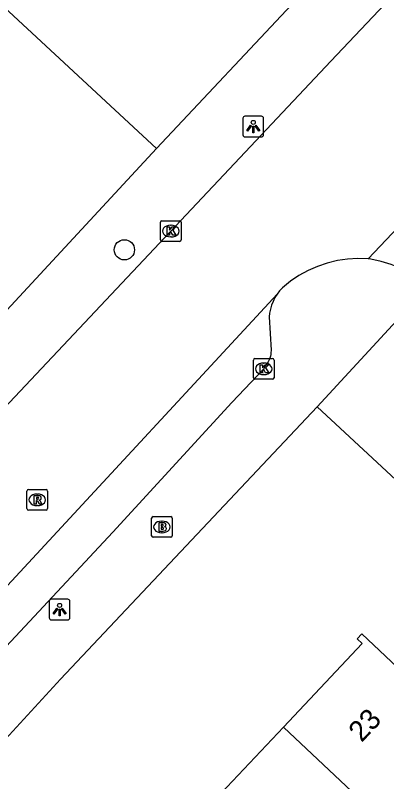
# Model space of a CAD drawing. Extents: x 159222 to 160346, y 381249 to 382166.
# Drawn here: x 159820.63 to 159838.58, y 381687.69 to 381724.77 of the extents above; entities that cross this region are included whole.
import ezdxf

# ---------------------------------------------------------------- set-up
doc = ezdxf.new("R2010")
doc.units = 0
for name, color, linetype in [('IMGEO_Boom', 7, 'Continuous'), ('IMGEO_Brandkraan', 7, 'Continuous'), ('IMGEO_Kolk', 7, 'Continuous'), ('IMGEO_Lichtpunt', 7, 'Continuous'), ('IMGEO_Pand', 7, 'Continuous'), ('IMGEO_Pand_nummerreeks', 7, 'Continuous'), ('IMGEO_Rijbaan_lokaal_gesloten', 7, 'Continuous'), ('IMGEO_Rijbaan_lokaal_open', 7, 'Continuous'), ('IMGEO_Rioolput', 7, 'Continuous'), ('IMGEO_Voetpad_open', 7, 'Continuous')]:
    doc.layers.add(name, color=color, linetype=linetype)

msp = doc.modelspace()

# ---------------------------------------------------------------- linework, layer by layer
at = {"layer": 'IMGEO_Boom'}
msp.add_circle((159825.903, 381713.424), 0.489, dxfattribs=at)
at = {"layer": 'IMGEO_Brandkraan'}
for p, q in [((159827.218, 381699.588), (159827.218, 381700.44)), ((159827.293, 381700.514), (159828.145, 381700.514)), ((159828.219, 381700.44), (159828.219, 381699.588)), ((159827.706, 381700.294), (159827.731, 381700.294)), ((159827.729, 381699.734), (159827.704, 381699.734)), ((159828.145, 381699.514), (159827.293, 381699.514))]:
    msp.add_line(p, q, dxfattribs=at)
for points in [[(159827.218, 381699.588), (159827.218, 381700.44)], [(159827.293, 381700.514), (159828.145, 381700.514)], [(159828.219, 381700.44), (159828.219, 381699.588)], [(159827.566, 381700.214), (159827.566, 381699.814), (159827.779, 381699.814)], [(159827.797, 381700.214), (159827.566, 381700.214)], [(159827.745, 381700.133), (159827.691, 381700.133), (159827.691, 381700.057)], [(159827.691, 381700.057), (159827.744, 381700.057)], [(159827.753, 381699.981), (159827.691, 381699.981), (159827.691, 381699.9)], [(159827.691, 381699.9), (159827.753, 381699.9)], [(159828.145, 381699.514), (159827.293, 381699.514)]]:
    msp.add_lwpolyline(points, dxfattribs=at)
for centre, radius, start, end in [((159827.295, 381700.438), 0.0765, 91.552, 178.448), ((159827.295, 381700.438), 0.0765, 91.552, 178.448), ((159828.143, 381700.438), 0.0765, 1.552, 88.448), ((159828.143, 381700.438), 0.0765, 1.552, 88.448), ((159827.746, 381700.095), 0.0379, 267.8285, 90.9355), ((159827.801, 381700.069), 0.145, 59.4692, 91.5367), ((159827.826, 381700.116), 0.0922, 285.5137, 58.1501), ((159827.831, 381699.924), 0.105, 301.3115, 78.989), ((159827.754, 381699.94), 0.0404, 269.8759, 90.5077), ((159827.785, 381700.065), 0.251, 268.6676, 293.5347), ((159827.295, 381699.59), 0.0765, 181.552, 268.448), ((159827.295, 381699.59), 0.0765, 181.552, 268.448), ((159828.143, 381699.59), 0.0765, 271.552, 358.448), ((159828.143, 381699.59), 0.0765, 271.552, 358.448)]:
    msp.add_arc(centre, radius, start, end, dxfattribs=at)
for centre, major_axis, ratio, start_param, end_param in [((159827.705, 381700.014), (-0.387, 0.002), 0.722429, 4.712389, 7.853982), ((159827.73, 381700.014), (-0.39, 0.002), 0.717154, 1.570796, 4.712389)]:
    msp.add_ellipse(centre, major_axis=major_axis, ratio=ratio, start_param=start_param, end_param=end_param, dxfattribs=at)
at = {"layer": 'IMGEO_Kolk'}
for p, q in [((159827.723, 381714.83), (159828.575, 381714.83)), ((159827.648, 381713.904), (159827.648, 381714.756)), ((159828.136, 381714.61), (159828.161, 381714.61)), ((159828.649, 381714.756), (159828.649, 381713.904)), ((159828.575, 381713.83), (159827.723, 381713.83)), ((159828.159, 381714.05), (159828.134, 381714.05)), ((159832.216, 381708.163), (159833.068, 381708.163)), ((159832.141, 381707.237), (159832.141, 381708.089)), ((159832.629, 381707.943), (159832.654, 381707.943)), ((159833.142, 381708.089), (159833.142, 381707.237)), ((159833.068, 381707.163), (159832.216, 381707.163)), ((159832.652, 381707.383), (159832.627, 381707.383))]:
    msp.add_line(p, q, dxfattribs=at)
for points in [[(159827.723, 381714.83), (159828.575, 381714.83)], [(159827.648, 381713.904), (159827.648, 381714.756)], [(159827.969, 381714.53), (159828.092, 381714.53), (159828.092, 381714.379), (159828.222, 381714.53), (159828.386, 381714.53), (159828.24, 381714.379), (159828.393, 381714.13), (159828.241, 381714.13), (159828.156, 381714.294), (159828.092, 381714.227), (159828.092, 381714.13), (159827.969, 381714.13), (159827.969, 381714.53)], [(159828.649, 381714.756), (159828.649, 381713.904)], [(159828.575, 381713.83), (159827.723, 381713.83)], [(159832.216, 381708.163), (159833.068, 381708.163)], [(159832.141, 381707.237), (159832.141, 381708.089)], [(159832.462, 381707.863), (159832.585, 381707.863), (159832.585, 381707.712), (159832.715, 381707.863), (159832.879, 381707.863), (159832.733, 381707.712), (159832.886, 381707.463), (159832.734, 381707.463), (159832.649, 381707.627), (159832.585, 381707.56), (159832.585, 381707.463), (159832.462, 381707.463), (159832.462, 381707.863)], [(159833.142, 381708.089), (159833.142, 381707.237)], [(159833.068, 381707.163), (159832.216, 381707.163)]]:
    msp.add_lwpolyline(points, dxfattribs=at)
for centre, start, end in [((159827.725, 381714.754), 91.552, 178.448), ((159827.725, 381714.754), 91.552, 178.448), ((159828.573, 381714.754), 1.552, 88.448), ((159828.573, 381714.754), 1.552, 88.448), ((159827.725, 381713.906), 181.552, 268.448), ((159827.725, 381713.906), 181.552, 268.448), ((159828.573, 381713.906), 271.552, 358.448), ((159828.573, 381713.906), 271.552, 358.448), ((159832.218, 381708.087), 91.552, 178.448), ((159832.218, 381708.087), 91.552, 178.448), ((159833.066, 381708.087), 1.552, 88.448), ((159833.066, 381708.087), 1.552, 88.448), ((159832.218, 381707.239), 181.552, 268.448), ((159832.218, 381707.239), 181.552, 268.448), ((159833.066, 381707.239), 271.552, 358.448), ((159833.066, 381707.239), 271.552, 358.448)]:
    msp.add_arc(centre, 0.0765, start, end, dxfattribs=at)
for centre, major_axis, ratio, start_param, end_param in [((159828.135, 381714.33), (-0.387, 0.002), 0.722429, 4.712389, 7.853982), ((159828.16, 381714.33), (-0.39, 0.002), 0.717154, 1.570796, 4.712389), ((159832.628, 381707.663), (-0.387, 0.002), 0.722429, 4.712389, 7.853982), ((159832.653, 381707.663), (-0.39, 0.002), 0.717154, 1.570796, 4.712389)]:
    msp.add_ellipse(centre, major_axis=major_axis, ratio=ratio, start_param=start_param, end_param=end_param, dxfattribs=at)
at = {"layer": 'IMGEO_Lichtpunt'}
for p, q in [((159831.635, 381719.79), (159831.635, 381718.983)), ((159831.635, 381719.79), (159831.635, 381718.983)), ((159832.537, 381719.885), (159831.729, 381719.885)), ((159832.537, 381719.885), (159831.729, 381719.885)), ((159832.631, 381718.983), (159832.631, 381719.79)), ((159832.631, 381718.983), (159832.631, 381719.79)), ((159831.729, 381718.889), (159832.537, 381718.889)), ((159831.729, 381718.889), (159832.537, 381718.889)), ((159822.272, 381696.42), (159822.272, 381695.613)), ((159822.272, 381696.42), (159822.272, 381695.613)), ((159823.174, 381696.515), (159822.366, 381696.515)), ((159823.174, 381696.515), (159822.366, 381696.515)), ((159823.268, 381695.613), (159823.268, 381696.42)), ((159823.268, 381695.613), (159823.268, 381696.42)), ((159822.366, 381695.519), (159823.174, 381695.519)), ((159822.366, 381695.519), (159823.174, 381695.519))]:
    msp.add_line(p, q, dxfattribs=at)
for points in [[(159832.009, 381719.454), (159832.048, 381719.426), (159831.86, 381719.164), (159831.822, 381719.191), (159832.009, 381719.454)], [(159832.111, 381719.406), (159832.158, 381719.406), (159832.158, 381719.084), (159832.111, 381719.084), (159832.111, 381719.406)], [(159832.221, 381719.426), (159832.259, 381719.453), (159832.446, 381719.191), (159832.407, 381719.163), (159832.221, 381719.426)], [(159822.646, 381696.084), (159822.685, 381696.056), (159822.497, 381695.794), (159822.459, 381695.821), (159822.646, 381696.084)], [(159822.748, 381696.036), (159822.795, 381696.036), (159822.795, 381695.714), (159822.748, 381695.714), (159822.748, 381696.036)], [(159822.858, 381696.056), (159822.896, 381696.083), (159823.083, 381695.821), (159823.044, 381695.793), (159822.858, 381696.056)]]:
    msp.add_lwpolyline(points, dxfattribs=at)
for centre in [(159832.134, 381719.588), (159822.771, 381696.218)]:
    msp.add_circle(centre, 0.0994, dxfattribs=at)
for centre, start, end in [((159831.729, 381719.79), 90, 180), ((159831.729, 381719.79), 90, 180), ((159832.537, 381719.79), 0, 90), ((159832.537, 381719.79), 0, 90), ((159831.729, 381718.983), 180, 270), ((159831.729, 381718.983), 180, 270), ((159832.537, 381718.983), 270, 0), ((159832.537, 381718.983), 270, 360), ((159822.366, 381696.42), 90, 180), ((159822.366, 381696.42), 90, 180), ((159823.174, 381696.42), 0, 90), ((159823.174, 381696.42), 0, 90), ((159822.366, 381695.613), 180, 270), ((159822.366, 381695.613), 180, 270), ((159823.174, 381695.613), 270, 0), ((159823.174, 381695.613), 270, 360)]:
    msp.add_arc(centre, 0.0946, start, end, dxfattribs=at)
at = {"layer": 'IMGEO_Pand'}
for points in [[(159827.45, 381718.318), (159816.282, 381728.697)], [(159820.214, 381710.509), (159827.45, 381718.318)], [(159838.544, 381685.667), (159842.408, 381689.769), (159842.636, 381689.554), (159842.804, 381689.732), (159837.387, 381694.835), (159837.163, 381694.597), (159837.402, 381694.372), (159833.594, 381690.33)], [(159829.482, 381685.965), (159833.594, 381690.33)], [(159833.594, 381690.33), (159838.544, 381685.667)]]:
    msp.add_lwpolyline(points, dxfattribs=at)
at = {"layer": 'IMGEO_Rijbaan_lokaal_gesloten'}
for points in [[(159804.355, 381688.92), (159806.94, 381691.739), (159815.887, 381701.285), (159819.093, 381704.705), (159820.61, 381706.317), (159835.884, 381722.548), (159839.079, 381725.943), (159851.927, 381739.596), (159861.976, 381750), (159867.295, 381755.549)], [(159843.184, 381718.791), (159837.692, 381712.986)], [(159837.692, 381712.986), (159837.193, 381713.002), (159836.694, 381712.973), (159836.2, 381712.9), (159835.714, 381712.783), (159835.241, 381712.623), (159834.784, 381712.421), (159834.346, 381712.179), (159833.932, 381711.9), (159833.545, 381711.584), (159833.411, 381711.436), (159833.291, 381711.277)], [(159833.291, 381711.277), (159808.817, 381684.831)]]:
    msp.add_lwpolyline(points, dxfattribs=at)
at = {"layer": 'IMGEO_Rijbaan_lokaal_open'}
msp.add_lwpolyline([(159840.574, 381711.703), (159840.167, 381712.014), (159839.735, 381712.288), (159839.279, 381712.521), (159838.805, 381712.714), (159838.315, 381712.863), (159837.814, 381712.967), (159837.692, 381712.986)], dxfattribs=at)
at = {"layer": 'IMGEO_Rioolput'}
for p, q in [((159821.191, 381700.901), (159821.191, 381701.753)), ((159821.266, 381701.827), (159822.118, 381701.827)), ((159821.679, 381701.607), (159821.704, 381701.607)), ((159822.192, 381701.753), (159822.192, 381700.901)), ((159822.118, 381700.827), (159821.266, 381700.827)), ((159821.702, 381701.047), (159821.677, 381701.047))]:
    msp.add_line(p, q, dxfattribs=at)
for points in [[(159821.191, 381700.901), (159821.191, 381701.753)], [(159821.266, 381701.827), (159822.118, 381701.827)], [(159821.78, 381701.525), (159821.528, 381701.527), (159821.528, 381701.127)], [(159822.192, 381701.753), (159822.192, 381700.901)], [(159821.528, 381701.127), (159821.652, 381701.127), (159821.652, 381701.289), (159821.663, 381701.289)], [(159821.706, 381701.446), (159821.652, 381701.446), (159821.652, 381701.365)], [(159821.652, 381701.365), (159821.704, 381701.365)], [(159821.71, 381701.26), (159821.781, 381701.127), (159821.921, 381701.127), (159821.856, 381701.253)], [(159822.118, 381700.827), (159821.266, 381700.827)]]:
    msp.add_lwpolyline(points, dxfattribs=at)
for centre, radius, start, end in [((159821.268, 381701.751), 0.0765, 91.552, 178.448), ((159821.268, 381701.751), 0.0765, 91.552, 178.448), ((159821.779, 381701.415), 0.109, 350.3612, 89.416), ((159822.116, 381701.751), 0.0765, 1.552, 88.448), ((159822.116, 381701.751), 0.0765, 1.552, 88.448), ((159821.662, 381701.236), 0.0533, 26.0293, 88.6989), ((159821.688, 381701.554), 0.19, 274.7715, 282.9687), ((159821.712, 381701.35), 0.0964, 77.0061, 93.1865), ((159821.726, 381701.407), 0.0378, 276.6634, 79.6772), ((159821.777, 381701.415), 0.112, 277.5842, 350.9817), ((159821.761, 381701.2), 0.108, 29.5134, 73.7905), ((159821.268, 381700.903), 0.0765, 181.552, 268.448), ((159821.268, 381700.903), 0.0765, 181.552, 268.448), ((159822.116, 381700.903), 0.0765, 271.552, 358.448), ((159822.116, 381700.903), 0.0765, 271.552, 358.448)]:
    msp.add_arc(centre, radius, start, end, dxfattribs=at)
for centre, major_axis, ratio, start_param, end_param in [((159821.678, 381701.327), (-0.387, 0.002), 0.722429, 4.712389, 7.853982), ((159821.703, 381701.327), (-0.39, 0.002), 0.717154, 1.570796, 4.712389)]:
    msp.add_ellipse(centre, major_axis=major_axis, ratio=ratio, start_param=start_param, end_param=end_param, dxfattribs=at)
at = {"layer": 'IMGEO_Voetpad_open'}
for points in [[(159834.247, 381725.568), (159827.45, 381718.318)], [(159833.291, 381711.277), (159833.185, 381711.108), (159833.095, 381710.93), (159833.021, 381710.745), (159832.965, 381710.553), (159832.925, 381710.358), (159832.904, 381710.174), (159832.993, 381708.574), (159832.994, 381708.55), (159832.991, 381708.456), (159832.98, 381708.363), (159832.961, 381708.271), (159832.933, 381708.181), (159832.898, 381708.094), (159832.855, 381708.01), (159832.804, 381707.931), (159832.747, 381707.856), (159832.641, 381707.663), (159831.097, 381706.031), (159825.354, 381699.76), (159814.36, 381687.992), (159810.255, 381683.514)], [(159839.254, 381710.203), (159835.227, 381705.82)], [(159808.447, 381676.973), (159822.816, 381692.641), (159835.227, 381705.82)], [(159835.227, 381705.82), (159880.768, 381663.542)]]:
    msp.add_lwpolyline(points, dxfattribs=at)

# ---------------------------------------------------------------- texts
at = {"layer": 'IMGEO_Pand_nummerreeks'}
msp.add_text('23', height=1, rotation=46.7084, dxfattribs=at).set_placement((159837.371, 381689.555))

doc.saveas('drawing.dxf')
